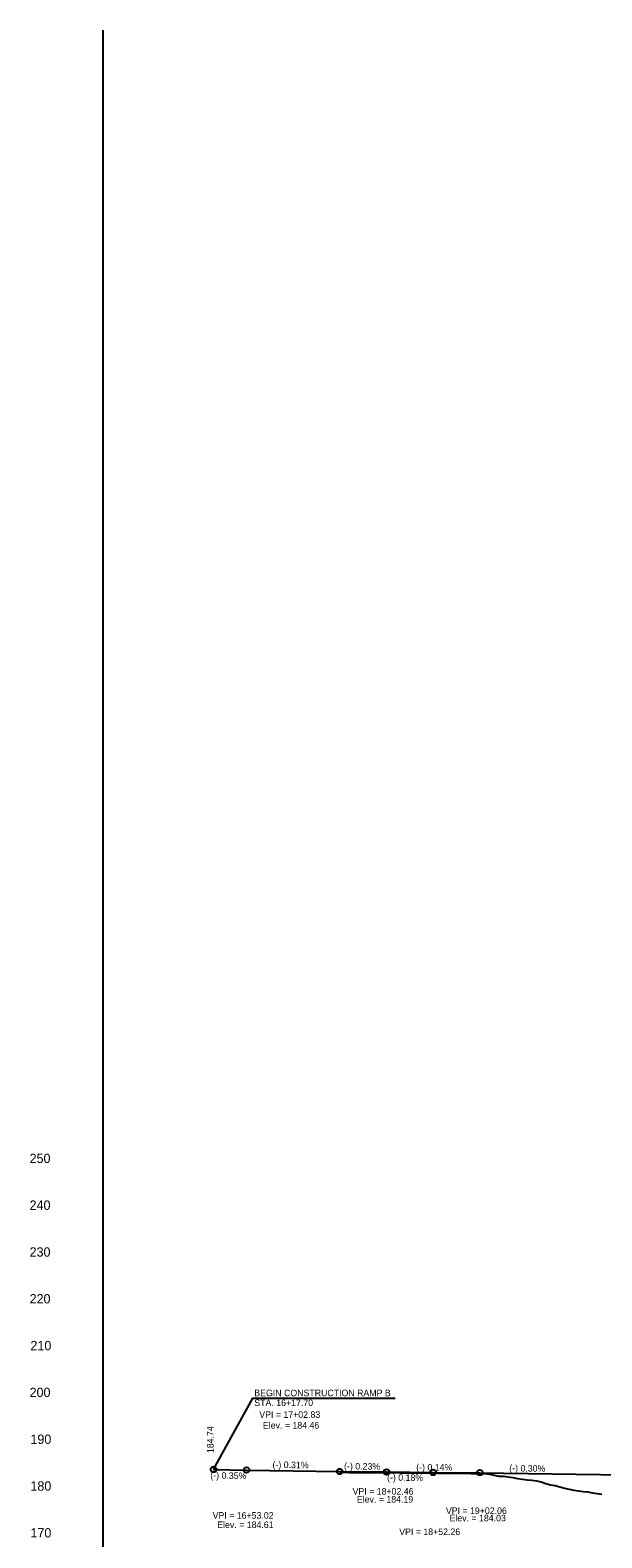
# Model space of a CAD drawing. Extents: x 69 to 2003113, y 512 to 837401.
# Drawn here: x 1923594 to 1924205, y 792764 to 794374 of the extents above; entities that cross this region are included whole.
import ezdxf

# ---------------------------------------------------------------- set-up
doc = ezdxf.new("R2010")
doc.units = 0
for name, color, linetype in [('BR_AUTO DIMENSION', 7, 'Continuous'), ('BR_BORDER LINES', 7, 'Continuous'), ('BR_CENTER LINE BASELINE', 7, 'Continuous'), ('BR_GRID DOTS', 7, 'Continuous'), ('BR_GRID LINES', 7, 'Continuous'), ('BR_TEXT', 7, 'Continuous'), ('MISCELLANEOUS', 7, 'Continuous'), ('RD_SHT_IplotShp', 7, 'Continuous')]:
    doc.layers.add(name, color=color, linetype=linetype)

msp = doc.modelspace()

# ---------------------------------------------------------------- linework, layer by layer
at = {"layer": 'BR_AUTO DIMENSION'}
msp.add_line((1923672.4, 791412.9), (1923672.4, 794374.1), dxfattribs=at)
at = {"layer": 'BR_BORDER LINES'}
msp.add_line((1923672.4, 792662.9), (1923672.4, 793912.9), dxfattribs=at)
at = {"layer": 'BR_CENTER LINE BASELINE'}
for centre in [(1923790.1, 792836.6), (1923825.4, 792836), (1923924.7, 792834.4), (1923974.8, 792833.9), (1924024.6, 792833.4), (1924074.4, 792833.1)]:
    msp.add_circle(centre, 3, dxfattribs=at)
at = {"layer": 'BR_GRID DOTS'}
msp.add_lwpolyline([(1923790.1, 792836.6), (1923832.1, 792912.9), (1923983.9, 792912.9)], dxfattribs=at)
at = {"layer": 'BR_GRID LINES'}
for p, q in [((1923924.7, 792834.4), (1923974.8, 792833.9)), ((1923974.8, 792833.9), (1924024.6, 792833.4)), ((1924024.6, 792833.4), (1924074.4, 792833.1)), ((1924074.4, 792833.1), (1924228.8, 792830.8))]:
    msp.add_line(p, q, dxfattribs=at)
msp.add_lwpolyline([(1923790.1, 792836.6), (1923825.4, 792836), (1923875.2, 792835.2), (1923924.7, 792834.4)], dxfattribs=at)
at = {"layer": 'BR_TEXT'}
msp.add_lwpolyline([(1923924.7, 792833.5), (1923929.7, 792833.6), (1923934.7, 792833.5), (1923939.7, 792833.4), (1923944.7, 792833.4), (1923949.7, 792833.4), (1923954.7, 792833.4), (1923959.7, 792833.4), (1923964.7, 792833.4), (1923969.7, 792833.4), (1923974.7, 792833.3), (1923979.7, 792833.3), (1923984.7, 792833.2), (1923989.7, 792833.1), (1923994.7, 792833.1), (1923999.7, 792833.1), (1924004.7, 792833), (1924009.7, 792833), (1924014.7, 792832.9), (1924019.7, 792832.9), (1924024.7, 792832.8), (1924029.7, 792832.7), (1924034.7, 792832.6), (1924039.7, 792832.6), (1924044.7, 792832.6), (1924049.7, 792832.6), (1924054.7, 792832.6), (1924059.7, 792832.5), (1924064.7, 792832.4), (1924069.7, 792832.3), (1924074.7, 792832.3), (1924079.7, 792832.2), (1924084.7, 792831.5), (1924089.7, 792830.5), (1924094.7, 792829.5), (1924099.7, 792829.5), (1924104.7, 792828.7), (1924109.7, 792828), (1924114.7, 792826.9), (1924119.7, 792826.1), (1924124.7, 792825.6), (1924129.7, 792825.1), (1924134.7, 792824.3), (1924139.7, 792823.2), (1924144.7, 792821.6), (1924149.7, 792820.2), (1924154.7, 792819.3), (1924159.7, 792818.1), (1924164.7, 792816.7), (1924169.7, 792815.4), (1924174.7, 792814.5), (1924179.7, 792813.8), (1924184.7, 792813.2), (1924189.7, 792812.6), (1924194.7, 792811.7), (1924199.7, 792811), (1924204.7, 792810.3)], dxfattribs=at)

# ---------------------------------------------------------------- texts
at = {"layer": 'BR_CENTER LINE BASELINE'}
for s, rotation, p in [('(-) 0.31%', 359.1258, (1923853, 792838.3)), ('(-) 0.23%', 359.348, (1923929.4, 792836.7)), ('(-) 0.14%', 359.6088, (1924006.4, 792835.5)), ('(-) 0.35%', 359.0105, (1923786.6, 792826.9)), ('(-) 0.18%', 359.4765, (1923975.3, 792824.6)), ('(-) 0.30%', 359.1406, (1924105.7, 792834.6))]:
    msp.add_text(s, height=7, rotation=rotation, dxfattribs=at).set_placement(p)
at = {"layer": 'MISCELLANEOUS'}
for s, p in [('250', (1923593.7, 793163.9)), ('240', (1923593.7, 793113.9)), ('230', (1923593.7, 793063.9)), ('220', (1923593.7, 793013.9)), ('210', (1923594.6, 792963.9)), ('200', (1923593.7, 792913.9)), ('190', (1923594.6, 792863.9)), ('180', (1923594.6, 792813.9)), ('170', (1923594.6, 792763.9))]:
    msp.add_text(s, height=10, dxfattribs=at).set_placement(p)
at = {"layer": 'RD_SHT_IplotShp'}
for s, p in [('STA. 16+17.70', (1923833.6, 792904.3)), ('BEGIN CONSTRUCTION RAMP B', (1923833.6, 792914.8)), ('VPI = 17+02.83', (1923838.9, 792891.7)), ('Elev. = 184.46', (1923842.8, 792880.2)), ('VPI = 18+02.46', (1923938.5, 792809.7)), ('Elev. = 184.19', (1923943.1, 792801.2)), ('VPI = 19+02.06', (1924038.1, 792789)), ('VPI = 16+53.02', (1923789.1, 792784)), ('Elev. = 184.61', (1923794, 792774)), ('Elev. = 184.03', (1924042, 792781.2)), ('VPI = 18+52.26', (1923988.3, 792766.5))]:
    msp.add_text(s, height=7, dxfattribs=at).set_placement(p)
msp.add_text('184.74', height=7, rotation=90, dxfattribs=at).set_placement((1923790.1, 792854.1))

doc.saveas('drawing.dxf')
